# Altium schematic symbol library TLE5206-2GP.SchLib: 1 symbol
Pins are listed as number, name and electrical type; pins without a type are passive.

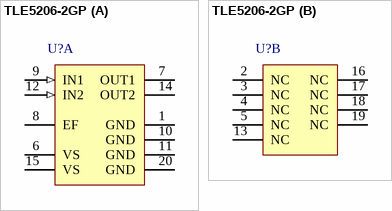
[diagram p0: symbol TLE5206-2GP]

## TLE5206-2GP
designator U?
5 A H-Bridge for DC-Motor Applications, 6 to 40 V, 220 mOhm RDS(on), PG-DSO-20-37, Reel, Green; Manufacturer: Infineon; PartNumber: TLE5206-2GP; Current Limit (min.): 6 A; Green: TRUE; Operating Range: 6 to 40 V; Quiescent Current (max.): 10 mA; RthJC (max): 5 K/W
footprint INF-PG-DSO-20-37_N (SOP, 20-Leads, Body 15.9x11mm, Pitch 1.27mm, Thermal Pad 15.84x6mm, IPC Medium Density)
footprint INF-PG-DSO-20-37_L (SOP, 20-Leads, Body 15.9x11mm, Pitch 1.27mm, Thermal Pad 15.84x6mm, IPC High Density)
footprint INF-PG-DSO-20-37_M (SOP, 20-Leads, Body 15.9x11mm, Pitch 1.27mm, Thermal Pad 15.84x6mm, IPC Low Density)
part A pins: 1 GND (power) "Ground; internally connected to tab", 6 VS (power) "Supply Voltage; block to GND", 7 OUT1 (power) "Output of Channel 1; Short-circuit protected; integrated freewheeling diodes for inductive loads.", 8 EF (oc) "Error Flag; TTL/CMOS compatible output for error detection; (open drain)", 9 IN1 (in) "Control Input 1; TTL/CMOS compatible", 10 GND (power) "Ground; internally connected to tab", 11 GND (power) "Ground; internally connected to tab", 12 IN2 (in) "Control Input 2; TTL/CMOS compatible", 14 OUT2 (power) "Output of Channel 2; Short-circuit protected; integrated freewheeling diodes for inductive loads.", 15 VS (power) "Supply Voltage; block to GND", 20 GND (power) "Ground; internally connected to tab"
part B pins: 2 NC "Not Connected", 3 NC "Not Connected", 4 NC "Not Connected", 5 NC "Not Connected", 13 NC "Not Connected", 16 NC "Not Connected", 17 NC "Not Connected", 18 NC "Not Connected", 19 NC "Not Connected"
